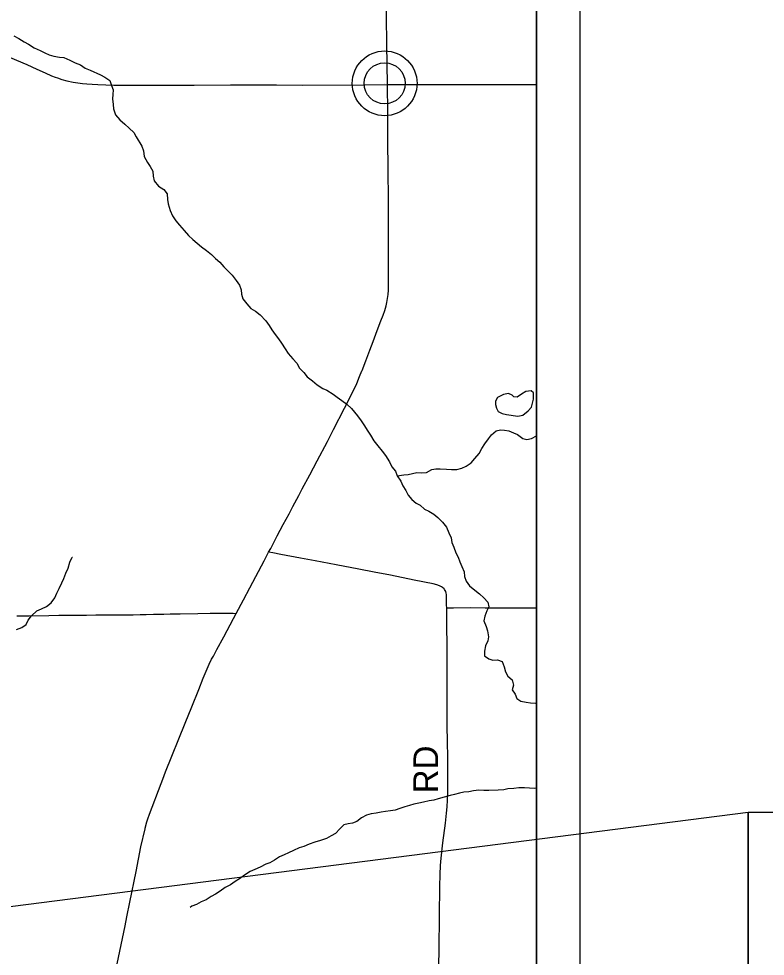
# Model space of a CAD drawing. Extents: x 0 to 34, y 0 to 22.
# Drawn here: x 7.711 to 9.426, y 18.065 to 20.22 of the extents above; entities that cross this region are included whole.
import ezdxf

# ---------------------------------------------------------------- set-up
doc = ezdxf.new("R2010")
doc.units = 0
for name, color, linetype in [('GM_X_Corporation', 7, 'Continuous'), ('GM_X_County_Road', 7, 'Continuous'), ('GM_X_Minor_Lake', 7, 'Continuous'), ('GM_X_Minor_River', 7, 'Continuous'), ('GM_X_State_Route', 7, 'Continuous'), ('GM_X_Township_Road', 7, 'Continuous'), ('GM_X_Township_Road_Text', 7, 'Continuous'), ('GM_X_Unincorporated', 7, 'Continuous'), ('GM_X_Unincorporated_Location', 7, 'Continuous'), ('SH_Data', 7, 'Continuous'), ('SH_Text', 7, 'Continuous')]:
    doc.layers.add(name, color=color, linetype=linetype)

msp = doc.modelspace()

# ---------------------------------------------------------------- linework, layer by layer
at = {"layer": 'GM_X_Corporation'}
msp.add_lwpolyline([(8.9, 17.5277), (8.9, 20.9), (5.0198, 20.9)], dxfattribs=at)
at = {"layer": 'GM_X_County_Road'}
msp.add_lwpolyline([(7.7064, 18.8473), (7.735, 18.8477), (7.7804, 18.8484), (7.8034, 18.8488), (7.8202, 18.8492), (7.8275, 18.8494), (7.8391, 18.8495), (7.8489, 18.8495), (7.8544, 18.8495), (7.8668, 18.8495), (7.8879, 18.8497), (7.8997, 18.8499), (7.9263, 18.8497), (7.9542, 18.8499), (7.9741, 18.8503), (7.9896, 18.8505), (8.0039, 18.8508), (8.0207, 18.8512), (8.0305, 18.8515), (8.0441, 18.8517), (8.0589, 18.8519), (8.0815, 18.8523), (8.1224, 18.8532), (8.1511, 18.8541), (8.1743, 18.854), (8.1942, 18.8541), (8.2035, 18.8536), (8.2105, 18.8533)], dxfattribs=at)
at = {"layer": 'GM_X_Minor_Lake'}
msp.add_line((8.8313, 19.3103), (8.8575, 19.3065), dxfattribs=at)
msp.add_lwpolyline([(8.8575, 19.3065), (8.8688, 19.3084), (8.8812, 19.3184), (8.8886, 19.3273), (8.8937, 19.3452), (8.8936, 19.3604), (8.8882, 19.3649), (8.8758, 19.3628), (8.866, 19.3574), (8.8558, 19.3501), (8.8486, 19.3511), (8.8448, 19.3549), (8.8364, 19.3582), (8.8243, 19.3561), (8.8104, 19.3491), (8.8063, 19.3407), (8.8064, 19.3331), (8.8088, 19.3252), (8.8126, 19.3173), (8.8218, 19.3124), (8.8313, 19.3103)], dxfattribs=at)
at = {"layer": 'GM_X_Minor_River'}
for points in [[(7.6998, 20.1804), (7.7116, 20.1745), (7.7238, 20.1666), (7.7333, 20.1611), (7.7463, 20.1532), (7.7604, 20.1466), (7.771, 20.1414), (7.7813, 20.1365), (7.7919, 20.134), (7.8045, 20.1311), (7.8147, 20.1305), (7.8284, 20.1246), (7.8406, 20.1183), (7.8528, 20.1135), (7.8638, 20.1064), (7.8749, 20.1016), (7.8985, 20.0912), (7.9091, 20.0853), (7.9202, 20.0778), (7.9245, 20.0664), (7.9276, 20.0566), (7.927, 20.0456), (7.9267, 20.0361), (7.9276, 20.0224), (7.9285, 20.0129), (7.9336, 19.9993), (7.9432, 19.9877), (7.955, 19.9776), (7.9646, 19.9686), (7.9753, 19.958), (7.9807, 19.9482), (7.9938, 19.9271), (7.9974, 19.9161), (7.9994, 19.9033), (8.0067, 19.8897), (8.0133, 19.8799), (8.0187, 19.8693), (8.02, 19.8579), (8.022, 19.8469), (8.0323, 19.8349), (8.0442, 19.8271), (8.0519, 19.8173), (8.0524, 19.8044), (8.054, 19.7941), (8.0587, 19.779), (8.0645, 19.7669), (8.0719, 19.7552), (8.0807, 19.7455), (8.0914, 19.7331), (8.101, 19.7218), (8.1106, 19.7124), (8.1209, 19.7038), (8.1305, 19.6955), (8.1423, 19.6873), (8.1538, 19.6783), (8.1633, 19.6686), (8.1729, 19.6603), (8.1821, 19.6494), (8.1921, 19.64), (8.2016, 19.6303), (8.2105, 19.6186), (8.2182, 19.6073), (8.2221, 19.5967), (8.223, 19.5872), (8.2261, 19.5763), (8.2353, 19.5646), (8.2438, 19.5541), (8.2548, 19.5474), (8.2655, 19.5395), (8.2786, 19.5256), (8.2863, 19.5147), (8.2924, 19.5049), (8.3001, 19.494), (8.3074, 19.4842), (8.3144, 19.4744), (8.3228, 19.4612), (8.3301, 19.4503), (8.3405, 19.4386), (8.3497, 19.4281), (8.3563, 19.4168), (8.3659, 19.4066), (8.3739, 19.3968), (8.3858, 19.3879), (8.3968, 19.3785), (8.4094, 19.3699), (8.4189, 19.3662)], [(8.4189, 19.3662), (8.4331, 19.3569), (8.4426, 19.3498), (8.4533, 19.3427), (8.4648, 19.3341), (8.4751, 19.3243), (8.4893, 19.307), (8.4978, 19.2954), (8.5051, 19.2841), (8.5116, 19.2743), (8.5193, 19.2626), (8.5267, 19.2494), (8.5359, 19.2385), (8.5459, 19.2264), (8.5536, 19.2163), (8.5624, 19.2019), (8.5682, 19.1902), (8.5763, 19.1801), (8.5806, 19.1691), (8.5887, 19.1571), (8.5933, 19.1461), (8.5999, 19.1359), (8.6053, 19.125), (8.6141, 19.1148), (8.6237, 19.1066), (8.6332, 19.1018), (8.6432, 19.0931), (8.6531, 19.0879), (8.6645, 19.0809), (8.6741, 19.0737), (8.6848, 19.0629), (8.6933, 19.0512), (8.6991, 19.0383), (8.7045, 19.027), (8.7058, 19.016), (8.7108, 19.0058), (8.7147, 18.9926), (8.7202, 18.9824), (8.7244, 18.9718), (8.7291, 18.9608), (8.7342, 18.9491), (8.7347, 18.9381), (8.7386, 18.9272), (8.7463, 18.9162), (8.7585, 18.9065), (8.7692, 18.8979), (8.7791, 18.8889), (8.7887, 18.8791), (8.7907, 18.8685), (8.7863, 18.859), (8.7815, 18.8471), (8.7793, 18.8361), (8.7844, 18.8229), (8.7879, 18.813), (8.79, 18.7994), (8.7882, 18.7899), (8.7834, 18.7784), (8.7809, 18.7666), (8.781, 18.756), (8.7905, 18.7485), (8.8, 18.746), (8.811, 18.7465), (8.8217, 18.7424), (8.826, 18.7303), (8.8288, 18.719), (8.8342, 18.7091), (8.8441, 18.7005), (8.8473, 18.688), (8.8444, 18.6774), (8.8513, 18.6676), (8.8552, 18.6577), (8.8647, 18.6518), (8.8769, 18.6496), (8.8867, 18.6479), (8.8973, 18.6472), (8.9, 18.6474)], [(8.5806, 19.1691), (8.5957, 19.1716), (8.6056, 19.1724), (8.6158, 19.1748), (8.6256, 19.1769), (8.6366, 19.1766), (8.6479, 19.1767), (8.6596, 19.1837), (8.6694, 19.1853), (8.6793, 19.1851), (8.6933, 19.1845), (8.705, 19.1839), (8.7172, 19.184), (8.7289, 19.1872), (8.7387, 19.1915), (8.7503, 19.1992), (8.7589, 19.2092), (8.7683, 19.2203), (8.7749, 19.2318), (8.7813, 19.2432), (8.7899, 19.254), (8.7969, 19.2635), (8.8074, 19.2724), (8.8173, 19.2748), (8.8267, 19.2741), (8.837, 19.2731), (8.8473, 19.2683), (8.8568, 19.2642), (8.869, 19.2549), (8.8785, 19.2531), (8.8891, 19.2555), (8.9, 19.261)], [(7.7062, 18.8164), (7.7179, 18.8211), (7.7281, 18.8276), (7.7329, 18.838), (7.7407, 18.8479), (7.7523, 18.8591), (7.7633, 18.8638), (7.7749, 18.8688), (7.7854, 18.8773), (7.7937, 18.8888), (7.7988, 18.8999), (7.804, 18.9106), (7.8099, 18.9235), (7.8144, 18.9335), (7.8192, 18.9457), (7.8243, 18.9575), (7.8287, 18.9712), (7.8339, 18.9823), (7.8347, 18.9827)], [(8.9, 18.4517), (8.8961, 18.4509), (8.8844, 18.4519), (8.873, 18.4525), (8.8601, 18.452), (8.848, 18.4507), (8.8348, 18.4498), (8.825, 18.4474), (8.8121, 18.4469), (8.7909, 18.4466), (8.7795, 18.4461), (8.7678, 18.4467), (8.7557, 18.4454), (8.7447, 18.4434), (8.7337, 18.4422), (8.7232, 18.4398), (8.7122, 18.4373), (8.702, 18.4349), (8.6884, 18.4306), (8.6744, 18.427), (8.6646, 18.4243), (8.654, 18.4226), (8.6408, 18.4194), (8.6302, 18.417), (8.6189, 18.4146), (8.6087, 18.4115), (8.5978, 18.4087), (8.5868, 18.4047), (8.5755, 18.4012), (8.5653, 18.3992), (8.5536, 18.3979), (8.5437, 18.3963), (8.532, 18.3942), (8.5207, 18.3926), (8.5097, 18.3898), (8.4981, 18.3836)], [(8.4981, 18.3836), (8.4879, 18.3751), (8.4777, 18.3712), (8.4679, 18.3699), (8.4577, 18.3675), (8.4483, 18.3579), (8.439, 18.3476), (8.4288, 18.3421), (8.4183, 18.3359), (8.4039, 18.3316), (8.3915, 18.3277), (8.3783, 18.3229), (8.3658, 18.3179), (8.3549, 18.3143), (8.3421, 18.3085), (8.3308, 18.303), (8.321, 18.298), (8.3097, 18.2937), (8.2984, 18.2863), (8.2882, 18.2801), (8.2784, 18.277), (8.2653, 18.2704), (8.2532, 18.2645), (8.2423, 18.2602), (8.2299, 18.2513), (8.2178, 18.2436), (8.2081, 18.2374), (8.1972, 18.2297), (8.1855, 18.2231), (8.1738, 18.2146), (8.1633, 18.208), (8.1531, 18.203), (8.1415, 18.1949), (8.1302, 18.1906), (8.1193, 18.184), (8.1087, 18.1804), (8.1046, 18.1773)]]:
    msp.add_lwpolyline(points, dxfattribs=at)
at = {"layer": 'GM_X_State_Route'}
for points in [[(8.5579, 20.0684), (8.5564, 20.1613), (8.5558, 20.224), (8.5552, 20.2831), (8.5543, 20.3943), (8.5538, 20.4312), (8.5536, 20.4574)], [(7.691, 20.1309), (7.7293, 20.1146), (7.7526, 20.1042), (7.7718, 20.0954), (7.7864, 20.0889), (7.7945, 20.0856), (7.8004, 20.0836), (7.8104, 20.0804), (7.8218, 20.0774), (7.8357, 20.0743), (7.8466, 20.0725), (7.8578, 20.0709), (7.8676, 20.0701), (7.8794, 20.0692), (7.8924, 20.0684), (7.9295, 20.0674), (8.014, 20.0671), (8.114, 20.0674), (8.1978, 20.0677)], [(8.1978, 20.0677), (8.2506, 20.0678), (8.3034, 20.0679), (8.3636, 20.0675), (8.5058, 20.0676), (8.5579, 20.0684)], [(8.4993, 19.4104), (8.4997, 19.4113), (8.5082, 19.434), (8.5174, 19.4584), (8.5248, 19.4781), (8.5346, 19.5037), (8.5428, 19.5252), (8.5479, 19.5385), (8.5517, 19.5496), (8.5547, 19.5597), (8.5566, 19.5675), (8.5584, 19.5772), (8.5595, 19.5858), (8.5602, 19.5957), (8.5607, 19.6093), (8.5603, 19.7072), (8.5601, 19.7904), (8.5594, 19.8854), (8.5592, 19.9276), (8.5589, 19.9739), (8.5588, 20.0043), (8.5579, 20.0684)], [(8.5579, 20.0684), (8.5636, 20.0684), (8.6215, 20.0686), (8.6717, 20.0687), (8.7245, 20.0687), (8.7711, 20.0687), (8.8277, 20.0688), (8.8668, 20.0688), (8.9, 20.0689)], [(8.4342, 19.276), (8.4594, 19.3247), (8.4684, 19.3424), (8.4719, 19.3493), (8.482, 19.3702), (8.4873, 19.3815), (8.4941, 19.3975), (8.4993, 19.4104)], [(7.9369, 18.048), (7.9553, 18.1349), (7.9595, 18.1556), (7.9664, 18.1897), (7.9806, 18.2604), (7.9917, 18.3164), (8.0011, 18.3584), (8.0014, 18.3599), (8.0055, 18.3742), (8.0078, 18.3814), (8.0116, 18.3919), (8.038, 18.4623), (8.0418, 18.4721), (8.0485, 18.4889), (8.0932, 18.6009), (8.1086, 18.6388), (8.1244, 18.678), (8.1348, 18.7046), (8.1412, 18.7201), (8.146, 18.7315), (8.1483, 18.7366), (8.1542, 18.7483), (8.1581, 18.7553), (8.1623, 18.7629), (8.1664, 18.7706), (8.182, 18.7996), (8.2044, 18.8418), (8.2105, 18.8533), (8.227, 18.8847), (8.2417, 18.9121), (8.2555, 18.9379), (8.2745, 18.9741), (8.2851, 18.9938), (8.2898, 19.0026), (8.3048, 19.0312), (8.3187, 19.0576), (8.3319, 19.0823), (8.3406, 19.0987), (8.3541, 19.1239), (8.3623, 19.1392), (8.3796, 19.1715), (8.3967, 19.2039), (8.42, 19.2485), (8.4342, 19.276)]]:
    msp.add_lwpolyline(points, dxfattribs=at)
at = {"layer": 'GM_X_Township_Road'}
for points in [[(8.6942, 18.8661), (8.694, 18.8722), (8.6937, 18.8834), (8.6938, 18.8865), (8.6935, 18.8966), (8.6928, 18.8998), (8.6918, 18.9035), (8.6892, 18.9079), (8.688, 18.9094), (8.6847, 18.9125), (8.6821, 18.9143), (8.6775, 18.9166), (8.6715, 18.9187), (8.663, 18.9208), (8.6192, 18.9299), (8.565, 18.941), (8.5277, 18.9481), (8.4924, 18.9552), (8.4399, 18.9652), (8.3922, 18.9739), (8.3586, 18.9802), (8.3128, 18.9887), (8.2945, 18.9921), (8.2851, 18.9938)], [(8.6757, 18.0285), (8.6768, 18.0957), (8.6773, 18.1441), (8.6778, 18.1783), (8.6784, 18.2056), (8.6785, 18.2255), (8.6792, 18.2535), (8.6802, 18.2739), (8.6816, 18.2906), (8.6854, 18.3258), (8.6911, 18.3708), (8.6939, 18.3943), (8.6953, 18.4085), (8.6962, 18.4241), (8.6964, 18.4409), (8.6965, 18.4701), (8.6966, 18.4906), (8.6965, 18.5217), (8.6959, 18.559), (8.6954, 18.5951), (8.6949, 18.6348), (8.6949, 18.6634), (8.6948, 18.6995), (8.6949, 18.7405), (8.695, 18.774), (8.695, 18.7877), (8.6946, 18.8163), (8.6946, 18.8418), (8.6944, 18.8604), (8.6942, 18.8661)], [(8.6942, 18.8661), (8.6993, 18.8662), (8.7096, 18.8663), (8.7494, 18.8665), (8.7825, 18.8663), (8.8226, 18.8663), (8.8567, 18.8661), (8.8934, 18.8662), (8.9, 18.8662)]]:
    msp.add_lwpolyline(points, dxfattribs=at)
at = {"layer": 'GM_X_Unincorporated'}
for radius in [0.0744, 0.0472]:
    msp.add_circle((8.5516, 20.0713), radius, dxfattribs=at)
at = {"layer": 'GM_X_Unincorporated_Location'}
msp.add_line((8.5516, 20.0713), (8.5516, 20.0713), dxfattribs=at)
at = {"layer": 'SH_Data'}
for p, q in [((9, 21), (9, 14)), ((8.9, 20.9), (8.9, 14.1))]:
    msp.add_line(p, q, dxfattribs=at)
at = {"layer": 'SH_Text'}
for points in [[(9.3865, 18.3957), (4.9237, 17.8249), (9.3865, 18.0457)], [(9.3865, 17.6957), (11.1242, 17.6957), (11.1242, 18.3957), (9.3865, 18.3957)]]:
    msp.add_lwpolyline(points, close=True, dxfattribs=at)

# ---------------------------------------------------------------- texts
at = {"layer": 'GM_X_Township_Road_Text'}
msp.add_text('RD', height=0.05682, rotation=90, dxfattribs=at).set_placement((8.6744, 18.4398))

doc.saveas('drawing.dxf')
